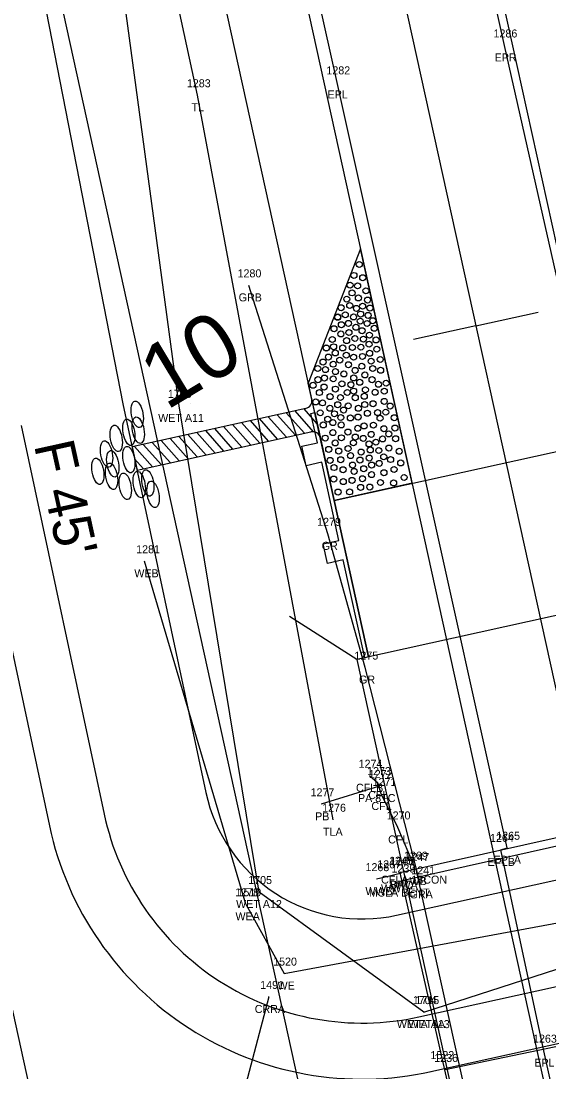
# Model space of a CAD drawing. Extents: x 2520975 to 2526538, y 881018 to 888064.
# Drawn here: x 2523710.8 to 2523776.7, y 885126.5 to 885257.8 of the extents above; entities that cross this region are included whole.
import ezdxf

# ---------------------------------------------------------------- set-up
doc = ezdxf.new("R2010")
doc.units = 0
for name, color, linetype in [('RD_EV_JurisArea', 7, 'Continuous'), ('RD_EX_BldgApp', 7, 'Continuous'), ('RD_EX_BldgApp_txCode', 7, 'Continuous'), ('RD_EX_Bridge', 7, 'Continuous'), ('RD_EX_Bridge_txCode', 7, 'Continuous'), ('RD_EX_Conc', 7, 'Continuous'), ('RD_EX_Conc_txCode', 7, 'Continuous'), ('RD_EX_DR_Pipe', 7, 'Continuous'), ('RD_EX_DR_Pipe_txCode', 7, 'Continuous'), ('RD_EX_DV_Prop', 7, 'Continuous'), ('RD_EX_GuardRail', 7, 'Continuous'), ('RD_EX_GuardRail_txCode', 7, 'Continuous'), ('RD_EX_H2O', 7, 'Continuous'), ('RD_EX_H2O_txCode', 7, 'Continuous'), ('RD_EX_H2O_WetLd_txCode', 7, 'Continuous'), ('RD_EX_Misc', 7, 'Continuous'), ('RD_EX_Misc_txCode', 7, 'Continuous'), ('RD_EX_Road', 7, 'Continuous'), ('RD_EX_Road_txCode', 7, 'Continuous'), ('RD_EX_RW', 7, 'Continuous'), ('RD_EX_VEG', 7, 'Continuous'), ('RD_EX_VEG_txCode', 7, 'Continuous'), ('RD_HC_Cl', 7, 'Continuous'), ('RD_HC_Data_Tic', 7, 'Continuous'), ('RD_HC_TX_Sta50', 7, 'Continuous'), ('RD_PD_BCA', 7, 'Continuous'), ('RD_PD_Bridge', 7, 'Continuous'), ('RD_PD_CstnLmt', 7, 'Continuous'), ('RD_PD_DR_ErosCtrl', 7, 'Continuous'), ('RD_PD_Final_TrvlWay', 7, 'Continuous'), ('RD_PD_GR', 7, 'Continuous'), ('RD_PD_PaveShd', 7, 'Continuous'), ('RD_SMD_Locator', 7, 'Continuous')]:
    doc.layers.add(name, color=color, linetype=linetype)

# ---------------------------------------------------------------- blocks, each defined once
blk = doc.blocks.new('TBC1')
at = {"layer": 'RD_PD_GR'}
blk.add_lwpolyline([(12.5, 2.5), (15, 2.5), (15, 0.49), (25, 0.49), (25, 2.5), (27.5, 2.5), (27.5, 0.49), (31.25, 0.49), (31.25, 0), (0, 0), (0, 0.49), (12.5, 0.49)], close=True, dxfattribs=at)

msp = doc.modelspace()

# ---------------------------------------------------------------- linework, layer by layer
at = {"layer": 'RD_EV_JurisArea'}
for points in [[(2523761.17, 885134.03), (2523740.58, 885149.03), (2523730.55, 885209.77), (2523710.6, 885357.47), (2523698.09, 885411.19), (2523674.93, 885498.62), (2523657.6, 885564.24), (2523640.82, 885610.87), (2523583.66, 885726.91), (2523539.21, 885693.17), (2523494.42, 885646.98)], [(2523761.17, 885134.03), (2523808.21, 885149.21), (2523821.91, 885178.64), (2523802.85, 885236.55), (2523777.81, 885305.56), (2523748.2, 885444.32), (2523730.68, 885516.88), (2523708.64, 885617.3), (2523698.71, 885662.02), (2523727.83, 885665.82), (2523757.3, 885671.75)]]:
    msp.add_lwpolyline(points, dxfattribs=at)
at = {"layer": 'RD_EX_BldgApp'}
msp.add_lwpolyline([(2523776.68, 885077.92), (2523768.27, 885115.31), (2523760.2, 885151.9)], dxfattribs=at)
at = {"layer": 'RD_EX_Bridge'}
for points in [[(2523774.91, 885077.6), (2523821.2, 885087.83), (2523805.06, 885161.89), (2523758.15, 885151.44), (2523774.91, 885077.6)], [(2523758.38, 885151.39), (2523756.7, 885150.99), (2523755.23, 885150.64)]]:
    msp.add_lwpolyline(points, dxfattribs=at)
at = {"layer": 'RD_EX_Conc'}
msp.add_lwpolyline([(2523760.04, 885152.08), (2523757.9, 885157.1), (2523755.8, 885161.28), (2523755.4, 885162.64), (2523754.34, 885163.56)], dxfattribs=at)
at = {"layer": 'RD_EX_DR_Pipe'}
msp.add_line((2523755.61, 885162.27), (2523748.33, 885159.99), dxfattribs=at)
at = {"layer": 'RD_EX_DV_Prop'}
msp.add_line((2523683.66, 885252.46), (2523748.18, 884959.48), dxfattribs=at)
at = {"layer": 'RD_EX_GuardRail'}
for p, q in [((2523749.16, 885193.78), (2523739.25, 885224.82)), ((2523753.83, 885177.07), (2523749.16, 885193.78)), ((2523760.65, 885150.24), (2523753.83, 885177.07))]:
    msp.add_line(p, q, dxfattribs=at)
at = {"layer": 'RD_EX_H2O'}
msp.add_line((2523738.91, 885147.5), (2523726.24, 885190.35), dxfattribs=at)
for points in [[(2523738.91, 885147.5), (2523743.69, 885138.84), (2523816.36, 885152.29), (2523822.43, 885163.3), (2523826.93, 885206.61)], [(2523741.75, 885135.92), (2523732.18, 885099.57), (2523664.9, 885060.26), (2523614.86, 885022.02), (2523558.95, 884972.63), (2523560.62, 884942.42), (2523490.01, 884911.76)]]:
    msp.add_lwpolyline(points, dxfattribs=at)
at = {"layer": 'RD_EX_Misc'}
for p, q in [((2523758.45, 885150.47), (2523805.66, 885161.06)), ((2523810.71, 885136.57), (2523763.83, 885126.8))]:
    msp.add_line(p, q, dxfattribs=at)
at = {"layer": 'RD_EX_Road'}
for p, q in [((2523771.24, 885254.79), (2523751.35, 885344.92)), ((2523750.32, 885250.18), (2523730.02, 885340.63)), ((2523792.78, 885159.31), (2523771.24, 885254.79)), ((2523771.58, 885154.56), (2523750.32, 885250.18)), ((2523770.8, 885154.29), (2523771.58, 885154.56)), ((2523776.18, 885129.21), (2523770.8, 885154.29)), ((2523781.52, 885104.77), (2523776.18, 885129.21))]:
    msp.add_line(p, q, dxfattribs=at)
at = {"layer": 'RD_EX_RW'}
msp.add_line((2523683.66, 885252.46), (2523748.18, 884959.48), dxfattribs=at)
at = {"layer": 'RD_EX_VEG'}
msp.add_lwpolyline([(2523749.81, 885158.06), (2523732.86, 885248.57), (2523691.62, 885438.95), (2523639.52, 885601.04)], dxfattribs=at)
at = {"layer": 'RD_HC_Cl'}
msp.add_line((2523641.17, 885794.2), (2524197.76, 883266.56), dxfattribs=at)
at = {"layer": 'RD_HC_Data_Tic'}
for q in [(2523775.47, 885221.48), (2523759.85, 885218.04)]:
    msp.add_line((2523767.66, 885219.76), q, dxfattribs=at)
at = {"layer": 'RD_PD_BCA'}
msp.add_line((2523703.95, 885205.86), (2523714.34, 885157.3), dxfattribs=at)
msp.add_lwpolyline([(2523762.05, 885126.6), (2523810.84, 885137.34)], dxfattribs=at)
msp.add_arc((2523753.45, 885165.66), 40, 192.0677, 282.4185, dxfattribs=at)
at = {"layer": 'RD_PD_Bridge'}
for p, q in [((2523749.94, 885197.94), (2523792.91, 885207.4)), ((2523754.24, 885178.41), (2523749.94, 885197.94)), ((2523752.77, 885178.09), (2523744.35, 885183.47))]:
    msp.add_line(p, q, dxfattribs=at)
for points in [[(2523798.67, 885188.19), (2523752.77, 885178.09)], [(2523752.77, 885178.09), (2523780.73, 885051.13)]]:
    msp.add_lwpolyline(points, dxfattribs=at)
at = {"layer": 'RD_PD_CstnLmt'}
for p, q in [((2523704.35, 885308.21), (2523723.51, 885210.04)), ((2523723.51, 885210.04), (2523733.89, 885161.48))]:
    msp.add_line(p, q, dxfattribs=at)
msp.add_lwpolyline([(2523757.75, 885146.13), (2523806.54, 885156.87)], dxfattribs=at)
msp.add_arc((2523753.45, 885165.66), 20, 192.0677, 282.4185, dxfattribs=at)
at = {"layer": 'RD_PD_DR_ErosCtrl'}
msp.add_line((2523710.8, 885207.32), (2523721.18, 885158.76), dxfattribs=at)
msp.add_lwpolyline([(2523760.55, 885133.43), (2523809.33, 885144.17)], dxfattribs=at)
msp.add_arc((2523753.45, 885165.66), 33, 192.0677, 282.4185, dxfattribs=at)
at = {"layer": 'RD_PD_Final_TrvlWay'}
for p, q in [((2523636.68, 885619.27), (2523984.7, 884038.8)), ((2523720.24, 885490.91), (2524037.44, 884050.42)), ((2523696.8, 885485.75), (2524014, 884045.26))]:
    msp.add_line(p, q, dxfattribs=at)
at = {"layer": 'RD_PD_GR'}
msp.add_line((2523747.52, 885208.93), (2523699.13, 885428.66), dxfattribs=at)
at = {"layer": 'RD_PD_PaveShd'}
for p, q in [((2523753.25, 885229.39), (2523746.71, 885212.59)), ((2523759.7, 885200.09), (2523753.25, 885229.39)), ((2523747.36, 885209.66), (2523746.71, 885212.59)), ((2523746.38, 885209.44), (2523724.66, 885204.65)), ((2523747.82, 885207.53), (2523746.17, 885209.4)), ((2523748, 885206.73), (2523747.36, 885209.66)), ((2523742.86, 885205.6), (2523740.59, 885208.17)), ((2523743.98, 885205.84), (2523741.7, 885208.41)), ((2523745.09, 885206.09), (2523742.82, 885208.66)), ((2523746.21, 885206.34), (2523743.94, 885208.91)), ((2523747.37, 885206.53), (2523745.05, 885209.15)), ((2523736.16, 885204.12), (2523733.88, 885206.69)), ((2523737.27, 885204.36), (2523735, 885206.93)), ((2523738.39, 885204.61), (2523736.12, 885207.18)), ((2523739.51, 885204.86), (2523737.23, 885207.43)), ((2523740.63, 885205.1), (2523738.35, 885207.67)), ((2523741.74, 885205.35), (2523739.47, 885207.92)), ((2523748, 885206.73), (2523749.94, 885197.94)), ((2523749.94, 885197.94), (2523748, 885206.73)), ((2523725.29, 885201.72), (2523747.02, 885206.51)), ((2523730.57, 885202.88), (2523728.3, 885205.45)), ((2523731.69, 885203.13), (2523729.42, 885205.7)), ((2523732.81, 885203.38), (2523730.53, 885205.95)), ((2523733.92, 885203.62), (2523731.65, 885206.19)), ((2523735.04, 885203.87), (2523732.77, 885206.44)), ((2523724.66, 885204.65), (2523725.29, 885201.72)), ((2523727.22, 885202.14), (2523724.95, 885204.71)), ((2523728.34, 885202.39), (2523726.06, 885204.96)), ((2523729.46, 885202.64), (2523727.18, 885205.21)), ((2523726.1, 885201.9), (2523724.98, 885203.17)), ((2523759.7, 885200.09), (2523749.94, 885197.94))]:
    msp.add_line(p, q, dxfattribs=at)
for centre in [(2523753.08, 885227.43), (2523753.08, 885227.43), (2523752.41, 885226.06), (2523752.41, 885226.06), (2523751.93, 885224.85), (2523751.93, 885224.85), (2523752.87, 885224.76), (2523752.87, 885224.76), (2523753.51, 885225.78), (2523753.51, 885225.78), (2523752.18, 885223.88), (2523752.18, 885223.88), (2523753.92, 885224.14), (2523753.92, 885224.14), (2523750.81, 885222.03), (2523750.81, 885222.03), (2523751.52, 885223.1), (2523751.89, 885222.31), (2523751.89, 885222.31), (2523752.97, 885223.25), (2523752.97, 885223.25), (2523753.5, 885222.22), (2523753.5, 885222.22), (2523754.11, 885222.99), (2523754.11, 885222.99), (2523750.37, 885220.83), (2523750.38, 885220.87), (2523751.33, 885221.14), (2523751.33, 885221.14), (2523752.36, 885220.87), (2523752.36, 885220.87), (2523752.73, 885221.95), (2523752.73, 885221.95), (2523753.25, 885221.23), (2523753.25, 885221.23), (2523754.19, 885221.07), (2523754.19, 885221.07), (2523754.42, 885221.99), (2523754.42, 885221.99), (2523749.92, 885219.4), (2523749.92, 885219.4), (2523750.84, 885219.9), (2523750.84, 885219.9), (2523751.73, 885220.07), (2523751.73, 885220.07), (2523752.67, 885219.58), (2523752.67, 885219.58), (2523753.2, 885220.35), (2523753.2, 885220.35), (2523754.06, 885220.06), (2523754.06, 885220.06), (2523754.77, 885220.41), (2523754.77, 885220.41), (2523754.95, 885219.46), (2523754.95, 885219.46), (2523749.7, 885218.06), (2523749.7, 885218.06), (2523750.78, 885218.75), (2523750.78, 885218.75), (2523751.79, 885218.93), (2523751.79, 885218.93), (2523752.53, 885218.18), (2523752.53, 885218.18), (2523753.43, 885219.15), (2523753.43, 885219.15), (2523753.6, 885218.1), (2523753.6, 885218.1), (2523754.34, 885218.6), (2523754.34, 885218.6), (2523748.95, 885216.99), (2523748.96, 885217), (2523749.87, 885217.15), (2523749.87, 885217.15), (2523751.01, 885217), (2523751.01, 885217), (2523751.5, 885217.92), (2523751.5, 885217.92), (2523752.22, 885217.06), (2523752.22, 885217.06), (2523753.28, 885217.1), (2523753.28, 885217.1), (2523754.3, 885217.47), (2523754.3, 885217.47), (2523755.18, 885218), (2523755.18, 885218), (2523755.27, 885216.85), (2523755.27, 885216.85), (2523749.23, 885215.87), (2523749.23, 885215.87), (2523750.08, 885216.38), (2523750.08, 885216.38), (2523750.64, 885215.48), (2523750.64, 885215.48), (2523751.46, 885216.1), (2523751.46, 885216.1), (2523752.37, 885215.85), (2523752.37, 885215.85), (2523753.48, 885215.94), (2523753.48, 885215.94), (2523754.38, 885216.34), (2523754.38, 885216.34), (2523755.7, 885215.56), (2523755.7, 885215.56), (2523747.88, 885214.44), (2523747.88, 885214.44), (2523748.55, 885215.24), (2523748.55, 885215.24), (2523748.85, 885214.3), (2523748.85, 885214.3), (2523749.82, 885214.97), (2523749.82, 885214.97), (2523751.73, 885214.91), (2523751.73, 885214.91), (2523752.56, 885214.2), (2523752.56, 885214.2), (2523753.4, 885214.72), (2523753.4, 885214.72), (2523754.56, 885215.35), (2523754.56, 885215.35), (2523754.76, 885214.43), (2523754.76, 885214.43), (2523755.75, 885214.21), (2523755.75, 885214.21), (2523747.91, 885213.04), (2523747.91, 885213.04), (2523748.73, 885213.24), (2523748.73, 885213.24), (2523749.82, 885213.14), (2523749.82, 885213.14), (2523750.1, 885214.05), (2523750.1, 885214.05), (2523751.15, 885213.76), (2523751.15, 885213.76), (2523752.39, 885213.26), (2523752.39, 885213.26), (2523753.78, 885213.63), (2523753.78, 885213.63), (2523754.68, 885213.04), (2523754.68, 885213.04), (2523747.3, 885212.34), (2523747.3, 885212.34), (2523747.3, 885212.34), (2523748.67, 885212.12), (2523748.67, 885212.12), (2523750.09, 885211.86), (2523750.09, 885211.86), (2523750.91, 885212.52), (2523750.91, 885212.52), (2523752.03, 885212.41), (2523752.03, 885212.41), (2523752.37, 885211.61), (2523752.37, 885211.61), (2523753.14, 885212.71), (2523753.14, 885212.71), (2523753.84, 885211.77), (2523753.84, 885211.77), (2523755.48, 885212.46), (2523755.48, 885212.46), (2523756.21, 885211.6), (2523756.21, 885211.6), (2523756.44, 885212.6), (2523756.44, 885212.6), (2523747.64, 885210.26), (2523747.64, 885210.26), (2523748.09, 885211.43), (2523748.09, 885211.43), (2523749.43, 885210.92), (2523749.43, 885210.92), (2523750.73, 885210.81), (2523750.73, 885210.81), (2523751.57, 885211.44), (2523751.57, 885211.44), (2523752.58, 885210.78), (2523752.58, 885210.78), (2523753.71, 885210.96), (2523753.71, 885210.96), (2523755.06, 885211.47), (2523755.06, 885211.47), (2523756.2, 885210.33), (2523756.2, 885210.33), (2523748.19, 885208.9), (2523748.19, 885208.9), (2523748.49, 885210.14), (2523748.49, 885210.14), (2523749.4, 885209.47), (2523749.4, 885209.47), (2523750.38, 885209.91), (2523750.38, 885209.91), (2523751.11, 885209.24), (2523751.11, 885209.24), (2523751.7, 885209.77), (2523751.7, 885209.77), (2523752.97, 885209.47), (2523752.97, 885209.47), (2523753.76, 885209.93), (2523753.76, 885209.93), (2523754.8, 885210.03), (2523754.8, 885210.03), (2523755.38, 885208.92), (2523755.38, 885208.92), (2523756.4, 885208.98), (2523756.4, 885208.98), (2523756.94, 885209.74), (2523749.13, 885208.1), (2523749.13, 885208.1), (2523749.78, 885207.67), (2523749.78, 885207.67), (2523749.98, 885208.78), (2523749.98, 885208.78), (2523750.77, 885208.31), (2523750.77, 885208.31), (2523751.97, 885208.26), (2523751.97, 885208.26), (2523752.93, 885208.37), (2523752.93, 885208.37), (2523754.09, 885208.84), (2523754.09, 885208.84), (2523755.68, 885208.23), (2523755.68, 885208.23), (2523757.45, 885208.29), (2523757.45, 885208.29), (2523748.58, 885207.38), (2523748.58, 885207.38), (2523749.78, 885206.43), (2523749.78, 885206.43), (2523750.82, 885207.38), (2523750.82, 885207.38), (2523751.67, 885206.49), (2523751.67, 885206.49), (2523752.9, 885206.97), (2523752.9, 885206.97), (2523753.68, 885207.26), (2523753.68, 885207.26), (2523754.84, 885207.36), (2523754.84, 885207.36), (2523756.16, 885206.91), (2523756.16, 885206.91), (2523756.77, 885206.26), (2523756.77, 885206.26), (2523757.54, 885207), (2523757.54, 885207), (2523748.82, 885205.74), (2523748.82, 885205.74), (2523750.07, 885205.13), (2523750.07, 885205.13), (2523750.84, 885205.78), (2523750.84, 885205.78), (2523752.34, 885205.15), (2523752.34, 885205.15), (2523752.58, 885205.87), (2523752.58, 885205.87), (2523753.57, 885205.7), (2523753.57, 885205.7), (2523754.3, 885205.01), (2523754.3, 885205.01), (2523754.57, 885206.2), (2523754.57, 885206.2), (2523755.16, 885205.23), (2523755.16, 885205.23), (2523755.99, 885205.63), (2523755.99, 885205.63), (2523757.63, 885205.66), (2523757.63, 885205.66), (2523749.26, 885204.33), (2523749.26, 885204.33), (2523750.51, 885204.12), (2523750.51, 885204.12), (2523751.68, 885204.44), (2523751.68, 885204.44), (2523753.31, 885204), (2523753.31, 885204), (2523754.46, 885204.26), (2523755.52, 885204.19), (2523755.52, 885204.19), (2523756.78, 885204.5), (2523756.78, 885204.5), (2523758.07, 885204.09), (2523758.07, 885204.09), (2523749.44, 885202.96), (2523749.44, 885202.96), (2523750.76, 885203.04), (2523750.76, 885203.04), (2523751.99, 885203.55), (2523751.99, 885203.55), (2523752.24, 885202.37), (2523752.24, 885202.37), (2523753.17, 885203), (2523753.17, 885203), (2523754.32, 885203.25), (2523754.32, 885203.25), (2523754.62, 885202.37), (2523754.62, 885202.37), (2523755.57, 885202.58), (2523755.57, 885202.58), (2523756.14, 885203.4), (2523756.14, 885203.4), (2523757, 885203.06), (2523757, 885203.06), (2523758.26, 885202.64), (2523758.26, 885202.64), (2523749.92, 885202.06), (2523749.92, 885202.06), (2523751.05, 885201.79), (2523751.05, 885201.79), (2523752.44, 885201.58), (2523752.44, 885201.58), (2523753.64, 885201.92), (2523753.64, 885201.92), (2523754.61, 885201.18), (2523754.61, 885201.18), (2523756.17, 885201.42), (2523756.17, 885201.42), (2523757.43, 885201.82), (2523757.43, 885201.82), (2523749.89, 885200.63), (2523749.89, 885200.63), (2523751.08, 885200.3), (2523751.08, 885200.3), (2523752.18, 885200.46), (2523752.18, 885200.46), (2523753.48, 885200.66), (2523753.48, 885200.66), (2523755.73, 885200.19), (2523755.73, 885200.19), (2523757.38, 885200.14), (2523757.38, 885200.14), (2523758.69, 885200.82), (2523758.69, 885200.82), (2523750.43, 885199), (2523750.43, 885199), (2523750.43, 885199), (2523751.87, 885199.02), (2523751.87, 885199.02), (2523753.25, 885199.58), (2523753.25, 885199.58), (2523754.4, 885199.62), (2523754.4, 885199.62)]:
    msp.add_circle(centre, 0.375, dxfattribs=at)
for centre, start, end in [((2523746.16, 885210.42), 282.4481, 12.4185), ((2523747.24, 885205.54), 12.4185, 102.4481)]:
    msp.add_arc(centre, 1, start, end, dxfattribs=at)
for centre in [(2523725.32, 885208.71), (2523724.26, 885206.47), (2523724.26, 885206.47), (2523725.44, 885206.73), (2523722.69, 885205.7), (2523722.69, 885205.7), (2523721.48, 885203.75), (2523721.48, 885203.75), (2523722.25, 885202.53), (2523722.25, 885202.53), (2523724.26, 885203.06), (2523724.26, 885203.06), (2523720.39, 885201.6), (2523720.39, 885201.6), (2523722.1, 885200.97), (2523722.1, 885200.97), (2523723.82, 885199.71), (2523723.82, 885199.71), (2523725.57, 885199.94), (2523725.57, 885199.94), (2523726.64, 885200.14), (2523726.64, 885200.14), (2523727.29, 885198.71), (2523727.29, 885198.71)]:
    msp.add_ellipse(centre, major_axis=(-0.29, 1.65), ratio=0.429445, dxfattribs=at)
at = {"layer": 'RD_SMD_Locator'}
for centre in [(2523771.24, 885254.79), (2523750.32, 885250.18), (2523732.86, 885248.57), (2523739.25, 885224.82), (2523732.01, 885210.1), (2523749.16, 885193.78), (2523726.24, 885190.35), (2523753.83, 885177.07), (2523754.34, 885163.56), (2523755.4, 885162.64), (2523755.61, 885162.27), (2523755.8, 885161.28), (2523748.33, 885159.99), (2523749.81, 885158.06), (2523757.9, 885157.1), (2523770.8, 885154.29), (2523771.58, 885154.56), (2523760.04, 885152.08), (2523760.2, 885151.9), (2523755.23, 885150.64), (2523756.7, 885150.99), (2523758.15, 885151.44), (2523758.38, 885151.39), (2523758.45, 885150.47), (2523760.65, 885150.24), (2523740.58, 885149.03), (2523738.91, 885147.5), (2523738.91, 885147.5), (2523743.69, 885138.84), (2523741.75, 885135.92), (2523761.17, 885134.03), (2523761.17, 885134.03), (2523776.18, 885129.21), (2523763.32, 885127.16), (2523763.83, 885126.8)]:
    msp.add_circle(centre, 0.001, dxfattribs=at)

# ---------------------------------------------------------------- block references
at = {"layer": 'RD_PD_Bridge', "rotation": 102.41848259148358}
msp.add_blockref('TBC1', (2523754.24, 885178.41), dxfattribs=at)

# ---------------------------------------------------------------- texts
at = {"layer": 'RD_EX_BldgApp_txCode'}
for s, p in [('1247', (2523758.86, 885152.9)), ('WB', (2523759.36, 885149.9)), ('1522', (2523761.98, 885128.16))]:
    msp.add_text(s, height=1, dxfattribs=at).set_placement(p)
at = {"layer": 'RD_EX_Bridge_txCode'}
for s, p in [('1267', (2523755.33, 885151.99)), ('1245', (2523756.8, 885152.44)), ('1266', (2523756.98, 885152.39)), ('1268', (2523753.86, 885151.64)), ('WWA', (2523756.98, 885149.39)), ('BRC', (2523756.89, 885149.44)), ('WWB', (2523753.85, 885148.64)), ('WW', (2523755.8, 885148.99))]:
    msp.add_text(s, height=1, dxfattribs=at).set_placement(p)
at = {"layer": 'RD_EX_Conc_txCode'}
for s, p in [('1274', (2523753, 885164.56)), ('1273', (2523754.06, 885163.64)), ('1271', (2523754.74, 885162.28)), ('CFLB', (2523752.67, 885161.56)), ('CFL', (2523754.2, 885160.64)), ('CFL', (2523754.6, 885159.28)), ('1270', (2523756.51, 885158.1)), ('CFL', (2523756.69, 885155.1)), ('1269', (2523758.67, 885153.08)), ('CFLA 18CON', (2523755.81, 885150.08))]:
    msp.add_text(s, height=1, dxfattribs=at).set_placement(p)
at = {"layer": 'RD_EX_DR_Pipe_txCode'}
for s, p in [('1272', (2523754.27, 885163.27)), ('1277', (2523746.99, 885160.99)), ('PA 8TC', (2523752.92, 885160.27)), ('PB', (2523747.56, 885157.99))]:
    msp.add_text(s, height=1, dxfattribs=at).set_placement(p)
at = {"layer": 'RD_EX_GuardRail_txCode'}
for s, p in [('1280', (2523737.86, 885225.82)), ('GRB', (2523738, 885222.82)), ('1279', (2523747.81, 885194.78)), ('GR', (2523748.38, 885191.78)), ('1275', (2523752.48, 885178.07)), ('GR', (2523753.05, 885175.07)), ('1241', (2523759.59, 885151.24)), ('GRA', (2523759.38, 885148.24))]:
    msp.add_text(s, height=1, dxfattribs=at).set_placement(p)
at = {"layer": 'RD_EX_H2O_txCode'}
for s, p in [('1281', (2523725.18, 885191.35)), ('WEB', (2523724.95, 885188.35)), ('1278', (2523737.56, 885148.5)), ('1519', (2523737.85, 885148.5)), ('WEA', (2523737.6, 885145.5)), ('WEA', (2523737.6, 885145.5)), ('1520', (2523742.31, 885139.84)), ('1491', (2523740.69, 885136.92)), ('WE', (2523742.86, 885136.84)), ('CRRA', (2523740.01, 885133.92))]:
    msp.add_text(s, height=1, dxfattribs=at).set_placement(p)
at = {"layer": 'RD_EX_H2O_WetLd_txCode'}
for s, p in [('1706', (2523729.14, 885210.77)), ('WET A11', (2523727.93, 885207.77)), ('1705', (2523739.19, 885150.03)), ('WET A12', (2523737.68, 885147.03)), ('1704', (2523759.78, 885135.03)), ('1715', (2523760.1, 885135.03)), ('WETA A13', (2523757.78, 885132.03)), ('WET1A', (2523759.21, 885132.03))]:
    msp.add_text(s, height=1, dxfattribs=at).set_placement(p)
at = {"layer": 'RD_EX_Misc_txCode'}
for s, p in [('1239', (2523757.11, 885151.47)), ('MSLA BENT', (2523754.3, 885148.47)), ('1236', (2523762.46, 885127.8))]:
    msp.add_text(s, height=1, dxfattribs=at).set_placement(p)
at = {"layer": 'RD_EX_Road_txCode'}
for s, p in [('1286', (2523769.87, 885255.79)), ('EPR', (2523770.01, 885252.79)), ('1282', (2523748.97, 885251.18)), ('EPL', (2523749.11, 885248.18)), ('1264', (2523769.43, 885155.29)), ('1265', (2523770.21, 885155.56)), ('EPLB', (2523769.12, 885152.29)), ('EPLA', (2523769.88, 885152.56)), ('1263', (2523774.81, 885130.21)), ('EPL', (2523774.97, 885127.21))]:
    msp.add_text(s, height=1, dxfattribs=at).set_placement(p)
at = {"layer": 'RD_EX_VEG_txCode'}
for s, p in [('1283', (2523731.52, 885249.57)), ('TL', (2523732.09, 885246.57)), ('1276', (2523748.44, 885159.06)), ('TLA', (2523748.55, 885156.06))]:
    msp.add_text(s, height=1, dxfattribs=at).set_placement(p)
at = {"layer": 'RD_HC_TX_Sta50'}
msp.add_text('10', height=8, rotation=31.1184, dxfattribs=at).set_placement((2523728.92, 885209.12))
at = {"layer": 'RD_PD_CstnLmt'}
msp.add_text("F 45'", height=5, rotation=282.4185, dxfattribs=at).set_placement((2523712.38, 885204.89))

doc.saveas('drawing.dxf')
